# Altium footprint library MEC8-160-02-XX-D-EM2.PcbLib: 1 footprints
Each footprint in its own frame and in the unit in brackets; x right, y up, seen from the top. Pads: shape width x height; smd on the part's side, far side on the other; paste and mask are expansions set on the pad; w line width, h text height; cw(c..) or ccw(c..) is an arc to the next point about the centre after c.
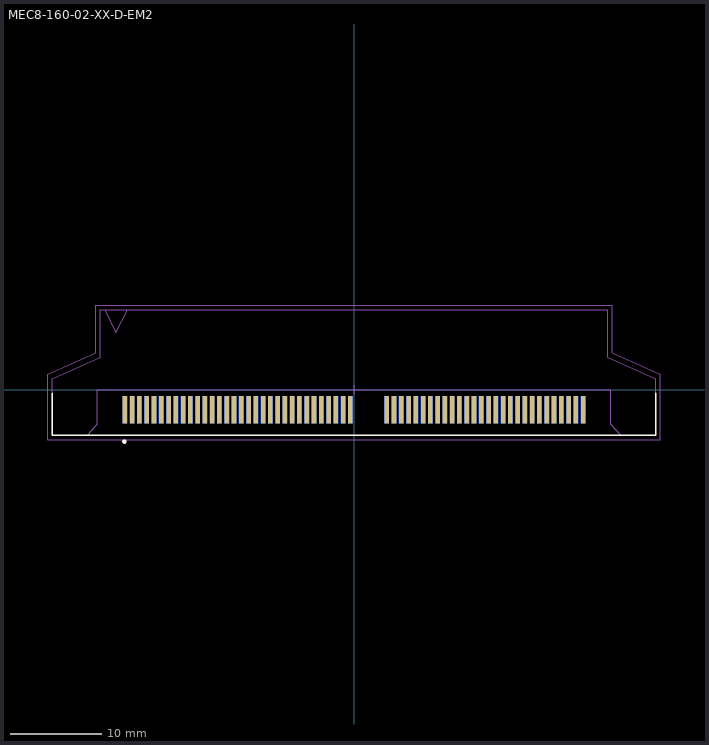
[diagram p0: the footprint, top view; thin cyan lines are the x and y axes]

## MEC8-160-02-XX-D-EM2 [mm] "0.80mm pitch, 120 pin, micro edge card; w/edge mounts"
height 8.65
pads (120):
  rect 0.5x3 smd mask+0: 1(-25.2,-2.2) 3(-24.4,-2.2) 5(-23.6,-2.2) 7(-22.8,-2.2) 9(-22,-2.2) 11(-21.2,-2.2) 13(-20.4,-2.2) 15(-19.6,-2.2) 17(-18.8,-2.2) 19(-18,-2.2) 21(-17.2,-2.2) 23(-16.4,-2.2) 25(-15.6,-2.2) 27(-14.8,-2.2) 29(-14,-2.2) 31(-13.2,-2.2) 33(-12.4,-2.2) 35(-11.6,-2.2) 37(-10.8,-2.2) 39(-10,-2.2) 41(-9.2,-2.2) 43(-8.4,-2.2) 45(-7.6,-2.2) 47(-6.8,-2.2) 49(-6,-2.2) 51(-5.2,-2.2) 53(-4.4,-2.2) 55(-3.6,-2.2) 57(-2.8,-2.2) 59(-2,-2.2) 61(-1.2,-2.2) 63(-0.4,-2.2) 65(3.6,-2.2) 67(4.4,-2.2) 69(5.2,-2.2) 71(6,-2.2) 73(6.8,-2.2) 75(7.6,-2.2) 77(8.4,-2.2) 79(9.2,-2.2) 81(10,-2.2) 83(10.8,-2.2) 85(11.6,-2.2) 87(12.4,-2.2) 89(13.2,-2.2) 91(14,-2.2) 93(14.8,-2.2) 95(15.6,-2.2) 97(16.4,-2.2) 99(17.2,-2.2) 101(18,-2.2) 103(18.8,-2.2) 105(19.6,-2.2) 107(20.4,-2.2) 109(21.2,-2.2) 111(22,-2.2) 113(22.8,-2.2) 115(23.6,-2.2) 117(24.4,-2.2) 119(25.2,-2.2)
  rect 0.5x3 smd far side mask+0: 2(-25.2,-2.2) 4(-24.4,-2.2) 6(-23.6,-2.2) 8(-22.8,-2.2) 10(-22,-2.2) 12(-21.2,-2.2) 14(-20.4,-2.2) 16(-19.6,-2.2) 18(-18.8,-2.2) 20(-18,-2.2) 22(-17.2,-2.2) 24(-16.4,-2.2) 26(-15.6,-2.2) 28(-14.8,-2.2) 30(-14,-2.2) 32(-13.2,-2.2) 34(-12.4,-2.2) 36(-11.6,-2.2) 38(-10.8,-2.2) 40(-10,-2.2) 42(-9.2,-2.2) 44(-8.4,-2.2) 46(-7.6,-2.2) 48(-6.8,-2.2) 50(-6,-2.2) 52(-5.2,-2.2) 54(-4.4,-2.2) 56(-3.6,-2.2) 58(-2.8,-2.2) 60(-2,-2.2) 62(-1.2,-2.2) 64(-0.4,-2.2) 66(3.6,-2.2) 68(4.4,-2.2) 70(5.2,-2.2) 72(6,-2.2) 74(6.8,-2.2) 76(7.6,-2.2) 78(8.4,-2.2) 80(9.2,-2.2) 82(10,-2.2) 84(10.8,-2.2) 86(11.6,-2.2) 88(12.4,-2.2) 90(13.2,-2.2) 92(14,-2.2) 94(14.8,-2.2) 96(15.6,-2.2) 98(16.4,-2.2) 100(17.2,-2.2) 102(18,-2.2) 104(18.8,-2.2) 106(19.6,-2.2) 108(20.4,-2.2) 110(21.2,-2.2) 112(22,-2.2) 114(22.8,-2.2) 116(23.6,-2.2) 118(24.4,-2.2) 120(25.2,-2.2)
Top Overlay:
  circle w0.25: c-25.25,-5.7 r0.125
  lines w0.2: -33.2,-0.4 -33.2,-5 33.2,-5 33.2,-0.4
Mechanical 12:
  lines w0.001: -33.2,-5 -33.2,1.2 -27.9,3.6 -27.9,8.8 27.9,8.8 27.9,3.6 33.2,1.2 33.2,-5 29.358,-5 28.25,-3.8 28.25,0.001 -28.25,0.001 -28.25,-3.8 -29.358,-5 -33.2,-5
Mechanical 13:
  lines w0.1: -33.2,-5 -33.2,1.2 -27.9,3.6 -27.9,8.8 -24.9,8.8 -26.2,6.3 -27.4,8.8 27.9,8.8 27.9,3.6 33.2,1.2 33.2,-5 29.358,-5 28.25,-3.8 28.25,0.001 -28.25,0.001 -28.25,-3.8 -29.358,-5 -33.2,-5
  text ".Designator" at 0.127,0.254 h1.52
Mechanical 15:
  lines w0.05: -0.5,0 0.5,0 ; 0,-0.5 0,0.5 ; -33.7,-5.5 33.7,-5.5 33.7,1.7 28.4,4.1 28.4,9.3 -28.4,9.3 -28.4,4.1 -33.7,1.7 -33.7,-5.5
Drill Drawing:
  lines w0.01: -35,0 -29.69,0 -29.69,-3.6 ccw(c-28.95,-3.6) -28.21,-3.6 -28.21,0 35,0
